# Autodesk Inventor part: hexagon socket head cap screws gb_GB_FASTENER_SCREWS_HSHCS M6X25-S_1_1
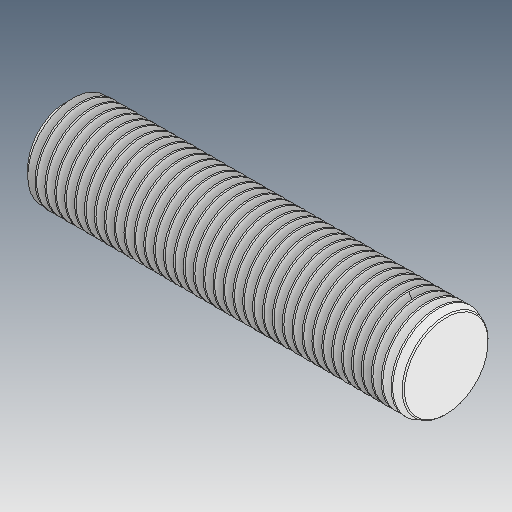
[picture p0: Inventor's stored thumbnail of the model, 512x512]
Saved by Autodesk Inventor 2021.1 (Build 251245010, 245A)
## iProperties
Created: 2021-05
Part Number: hexagon socket head cap screws gb_GB_FASTENER_SCREWS_HSHCS M6X25-S_1_1
Material: Ogólny
Document SubType Name: Modeling
Designer: user
Density: 1 g/cm^3
Appearance: Domyślna
Author: user
Revision Number: ÈÎºÎ
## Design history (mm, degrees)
feature "ÊäÈë1"
node "Bryła1"
